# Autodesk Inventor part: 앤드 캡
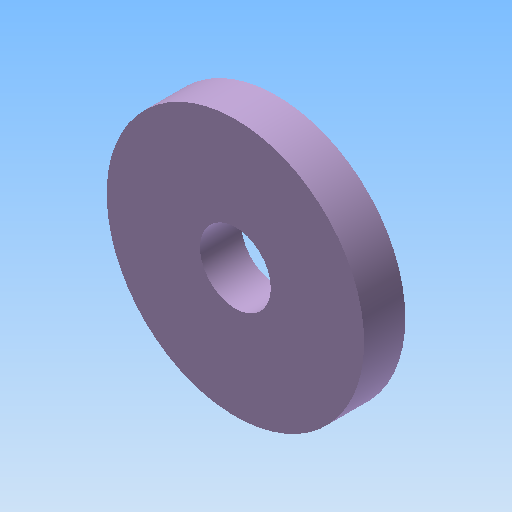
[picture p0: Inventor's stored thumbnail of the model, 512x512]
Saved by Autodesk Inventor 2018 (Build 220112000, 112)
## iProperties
Created: 2024-02
Part Number: 앤드 캡
Material: 강철, 연강
Document SubType Name: Modeling
Designer: mdu-01
Density: 1 g/cm^3
Appearance: 기본값(1)
Author: mdu-01
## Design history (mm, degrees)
sketch "스케치1" dims "d0" = 18.29645 (derived)
  geometry: L1 (19.05, 2.5)-(19.05, -2.5) reference; C1 r 10 at (10.25, 0); C2 r 2.75 at (10.25, 0); A1 r 6.5 centre (10.25, 0) between (16.25, 2.5) and (16.25, -2.5) reference; 2 further points
  constraints: 3 coincident, 2 centre point, 3 other
  dimensions: "d1" = 20 diameter of C1; "d2" = 5.5 diameter of C2
extrude "돌출1" new body sketch "스케치1" distance "d3" = 3.2; taper "d4" = 0 deg
node "솔리드1"
node "참조1"
node "참조2"
